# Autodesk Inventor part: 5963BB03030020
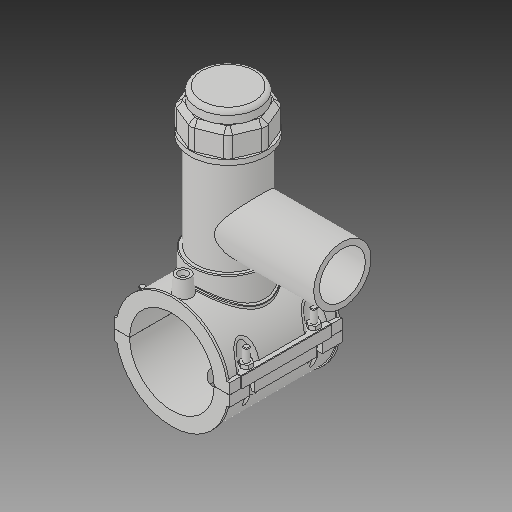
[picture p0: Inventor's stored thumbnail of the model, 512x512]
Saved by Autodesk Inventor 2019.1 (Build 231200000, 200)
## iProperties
Created: 2017-07
Part Number: 5963BB03030020
Material: Generic
Description: PLASSON TAPPING SADDLE 3''IPS x 2''IPS
Document SubType Name: Modeling
Designer: KIM
Mass: 1712.7 g
Surface Area: 2671.49 cm^2
Volume: 1712.7 cm^3
Density: 1 g/cm^3
Appearance: Default
Author: KIM
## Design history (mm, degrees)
derived "5963B.ipt"
feature "Solid1::5963B.ipt"
feature "Solid2::5963B.ipt"
feature "Solid4::5963B.ipt"
feature "Solid5::5963B.ipt"
tag "TaggingFeature1"
body "Solid1"
body "Solid2"
other parameters: "d0" = 88.7, "d2" = 120.904, "d3" = 22.175, "d4" = 118.11, "d5" = 0, "d6" = 0.1, "d8" = 0, "d19" = 6, "d20" = 6, "d21" = 70.866, "d23" = 0, "d24" = 35.433, "d26" = 0, "d29" = 3, "d30" = 29.56667, "d31" = 6, "d32" = 0, "d33" = 0, "d34" = 0.6, "d40" = 59.9612, "d41" = 79.83, "d43" = 0, "d45" = 0, "d47" = 128.521, "d70" = 15, "d72" = 0, "d73" = 6, "d75" = 5, "d76" = 0, "d77" = 4.435, "d78" = 74.35, "d79" = 15, "d80" = 47.244, "d82" = 5 deg, "d84" = 4, "d85" = 14, "d86" = 0, "d87" = 3, "d88" = 0, "d89" = 1, "d90" = 1, "d91" = 94.488, "d92" = 0, "d93" = 0.5, "d94" = 46.68421, "d96" = 117.6162, "d97" = 2.3622, "d98" = 0, "d102" = 0.887, "d120" = 140 deg, "d121" = 24.228, "d122" = 20 deg, "d123" = 230.62, "d124" = 69.186, "d126" = 0, "d143" = 91.361, "d145" = 20.46923, "d149" = 1.3305, "d150" = 22.51615, "d153" = 118.11, "d154" = 0, "d156" = 57.655, "d157" = 160 deg, "d159" = 5.322, "d161" = 1.3305, "d162" = 70.866, "d163" = 0, "d164" = 44.35, "d167" = 8.87, "d168" = 56.24878, "d170" = 3.2805, "d172" = 0, "d173" = 1, "d175" = 44.35, "d176" = 20 deg, "d177" = 6.209, "d178" = 26.61, "d180" = 0, "d183" = 10.644, "d184" = 4.9672, "d185" = 38.38575, "d186" = 38.38575, "d187" = 57.655, "d188" = 7.983, "d189" = 6.209, "d190" = 0, "d191" = 86.4825, "d193" = 6.1236, "d194" = 4.13385, "d195" = 90 deg, "d197" = 0, "d199" = 0, "d200" = 13.305, "d202" = 0, "d203" = 177.038, "d204" = 75.8385, "d205" = 55.881, "d206" = 67.8555, "d207" = 132.7785, "d208" = 138.08964, "d209" = 164.64534, "d210" = 68.6538, "d211" = 79.83, "d212" = 63.864, "d213" = 31.4766, "d216" = 0, "d217" = 8.87, "d218" = 4.435, "d219" = 0.887, "d222" = 88.7, "d224" = 0, "d230" = 5.322, "d233" = 6, "d236" = 60.452, "d237" = 35.433, "d238" = 6.02433, "d240" = 35.433, "d241" = 35.433, "d242" = 35.433, "d243" = 6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
